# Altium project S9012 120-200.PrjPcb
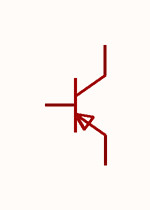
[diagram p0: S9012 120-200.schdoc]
1 sheet, 1 parts. Net scope: global (net labels, ports and power ports of the same name join across sheets).

## Sheet S9012 120-200.schdoc
size 127 x 101 mm

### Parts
Q?  s9012(range:120-200)  [SOT-23-3_L2.9-W1.6-P1.90-LS2.8-BR]  (value not drawn)

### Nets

Not connected (* = marked no-connect by the designer): Q? 1 2 3

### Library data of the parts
Q? = s9012(range:120-200): 晶体管类型:PNP;集电极电流(Ic):500mA;集射极击穿电压(Vceo):25V;耗散功率(Pd):300mW;直流电流增益(hFE):120;; Manufacturer: CJ(江苏长电/长晶); Symbol: S9012 120-200; AddInBom: yes; ModelId: 89cb27a44ab2466697082bb9fd73a7d0; ModelName: SOT-23-3L_L2.9-W1.6-H1.1-LS2.8-P0.95; ModelTransform: 114.173,110.236,0,90,0,0,0,0,0; type: PNP; Current - Collector(Ic): 500mA; Collector - Emitter Voltage VCEO: 25V; Pd - Power Dissipation: 300mW; DC Current Gain: 120; Transition frequency(fT): 150MHz; Current - Collector Cutoff: 100nA; Vce Saturation(VCE(sat)): 600mV; Emitter-Base Voltage(Vebo): 5V; Number: 1个PNP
